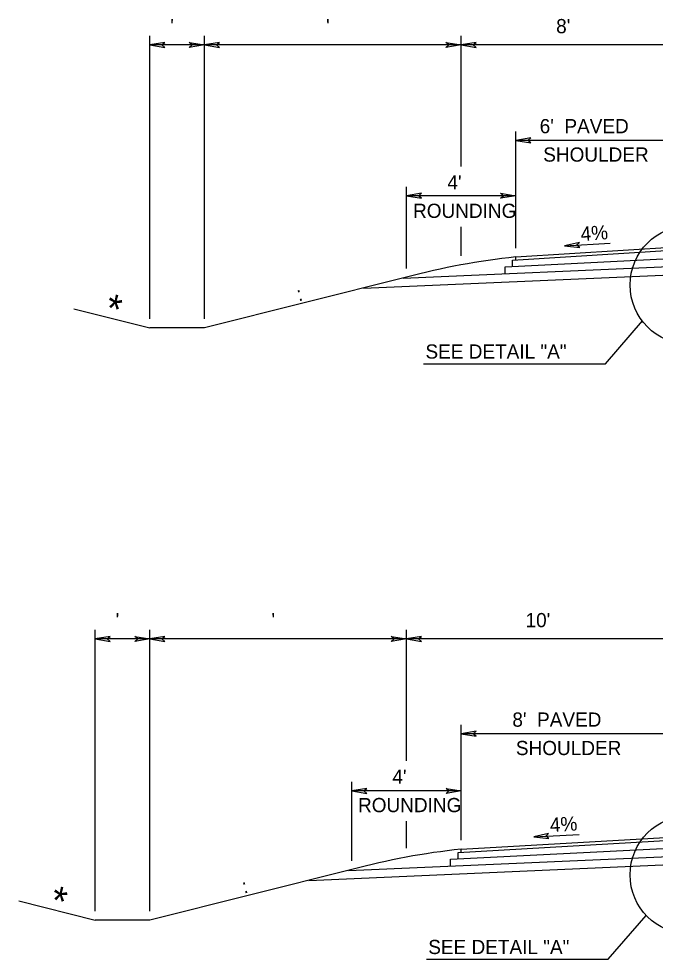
# Model space of a CAD drawing. Extents: x -592 to 1199, y -590 to 416.
# Drawn here: x -418.4 to -355.6, y 57.8 to 150.5 of the extents above; entities that cross this region are included whole.
import ezdxf

# ---------------------------------------------------------------- set-up
doc = ezdxf.new("R2010")
doc.units = 0
doc.layers.add('1', color=7, linetype='Continuous')
doc.layers.add('Des_ Drain_ Ftrs', color=7, linetype='Continuous')

msp = doc.modelspace()

# ---------------------------------------------------------------- linework, layer by layer
at = {"layer": '1'}
for p, q in [((-405.485, 120.951), (-405.485, 148.844)), ((-400.096, 120.951), (-400.096, 148.844)), ((-374.782, 135.971), (-374.782, 148.844)), ((-400.096, 147.964), (-405.485, 147.964)), ((-374.782, 147.964), (-400.096, 147.964)), ((-353.229, 147.964), (-374.782, 147.964)), ((-369.384, 127.944), (-369.384, 139.437)), ((-353.229, 138.557), (-369.384, 138.557)), ((-380.16, 125.935), (-380.16, 133.976)), ((-369.384, 133.096), (-380.16, 133.096)), ((-374.782, 127.165), (-374.782, 130.034)), ((-369.384, 127.064), (-353.234, 128.08)), ((-364.574, 128.144), (-360.084, 128.429)), ((-380.489, 124.973), (-326.288, 127.339)), ((-369.688, 126.744), (-353.469, 127.767)), ((-369.384, 126.764), (-369.384, 127.064)), ((-370.415, 126.097), (-354.173, 126.918)), ((-370.415, 125.413), (-370.415, 126.097)), ((-369.688, 126.134), (-369.688, 126.744)), ((-384.414, 123.991), (-354.876, 125.282)), ((-380.16, 125.055), (-400.096, 120.071)), ((-412.962, 121.94), (-405.485, 120.071)), ((-360.543, 116.54), (-356.895, 120.754)), ((-400.096, 120.071), (-405.485, 120.071)), ((-378.474, 116.54), (-360.543, 116.54)), ((-410.871, 62.58), (-410.871, 90.297)), ((-405.482, 62.58), (-405.482, 90.297)), ((-380.173, 77.411), (-380.173, 90.297)), ((-405.482, 89.417), (-410.871, 89.417)), ((-380.173, 89.417), (-405.482, 89.417)), ((-353.231, 89.417), (-380.173, 89.417)), ((-374.775, 69.563), (-374.775, 80.943)), ((-353.231, 80.063), (-374.775, 80.063)), ((-385.551, 67.555), (-385.551, 75.318)), ((-374.775, 74.438), (-385.551, 74.438)), ((-380.173, 68.785), (-380.173, 71.461)), ((-375.079, 68.366), (-353.471, 69.626)), ((-374.775, 68.684), (-353.237, 69.935)), ((-367.61, 69.9), (-363.119, 70.149)), ((-385.878, 66.593), (-326.29, 69.195)), ((-375.806, 67.718), (-354.175, 68.787)), ((-374.774, 68.383), (-374.774, 68.683)), ((-375.806, 67.033), (-375.806, 67.718)), ((-375.079, 67.754), (-375.079, 68.366)), ((-389.798, 65.613), (-354.879, 67.138)), ((-385.551, 66.675), (-405.482, 61.7)), ((-418.406, 63.584), (-410.871, 61.7)), ((-360.266, 57.846), (-356.526, 62.166)), ((-405.482, 61.7), (-410.871, 61.7)), ((-378.198, 57.846), (-360.266, 57.846))]:
    msp.add_line(p, q, dxfattribs=at)
for centre in [(-352.264, 124.302), (-352.266, 66.158)]:
    msp.add_circle(centre, 5.838, dxfattribs=at)
for centre in [(-362.501, 60.229), (-367.892, 1.849)]:
    msp.add_arc(centre, 67.188, 95.87953, 105.23809, dxfattribs=at)
at = {"layer": 'Des_ Drain_ Ftrs'}
for points in [[(-405.485, 147.964), (-403.997, 147.716), (-404.292, 147.964), (-403.997, 148.213)], [(-400.096, 147.964), (-401.585, 147.716), (-401.29, 147.964), (-401.585, 148.213)], [(-400.096, 147.964), (-398.608, 147.716), (-398.903, 147.964), (-398.608, 148.213)], [(-374.782, 147.964), (-376.271, 147.716), (-375.976, 147.964), (-376.271, 148.213)], [(-374.782, 147.964), (-373.294, 147.716), (-373.589, 147.964), (-373.294, 148.213)], [(-369.384, 138.557), (-367.895, 138.308), (-368.19, 138.557), (-367.895, 138.805)], [(-380.16, 133.096), (-378.672, 132.848), (-378.967, 133.096), (-378.672, 133.344)], [(-369.384, 133.096), (-370.872, 132.848), (-370.577, 133.096), (-370.872, 133.344)], [(-364.574, 128.144), (-363.073, 127.989), (-363.383, 128.219), (-363.104, 128.485)], [(-410.871, 89.417), (-409.383, 89.168), (-409.678, 89.417), (-409.383, 89.665)], [(-405.482, 89.417), (-406.971, 89.168), (-406.676, 89.417), (-406.971, 89.665)], [(-405.482, 89.417), (-403.994, 89.168), (-404.289, 89.417), (-403.994, 89.665)], [(-380.173, 89.417), (-381.662, 89.168), (-381.367, 89.417), (-381.662, 89.665)], [(-380.173, 89.417), (-378.685, 89.168), (-378.98, 89.417), (-378.685, 89.665)], [(-374.775, 80.063), (-373.286, 79.815), (-373.581, 80.063), (-373.286, 80.311)], [(-385.551, 74.438), (-384.063, 74.19), (-384.358, 74.438), (-384.063, 74.686)], [(-374.775, 74.438), (-376.263, 74.19), (-375.968, 74.438), (-376.263, 74.686)], [(-367.61, 69.9), (-366.111, 69.733), (-366.419, 69.965), (-366.138, 70.229)]]:
    msp.add_lwpolyline(points, close=True, dxfattribs=at)

# ---------------------------------------------------------------- texts
at = {"layer": '1'}
for s, p in [(" '", (-403.986, 149.116)), ("  '", (-389.135, 149.116)), ("8'", (-365.396, 149.116)), ("6'  PAVED", (-367.022, 139.257)), ('SHOULDER', (-366.673, 136.457)), ("4'", (-376.124, 133.712)), ('ROUNDING', (-379.513, 130.912)), ('SEE DETAIL "A"', (-378.289, 117.043)), (" '", (-409.372, 90.568)), ("  '", (-394.524, 90.568)), ("10'", (-368.417, 90.568)), ("8'  PAVED", (-369.719, 80.763)), ('SHOULDER', (-369.37, 77.963)), ("4'", (-381.553, 75.138)), ('ROUNDING', (-384.942, 72.338)), ('SEE DETAIL "A"', (-378.013, 58.35))]:
    msp.add_text(s, height=1.4, dxfattribs=at).set_placement(p)
for s, height, rotation, p in [('4%', 1.4, 3.91556, (-362.941, 128.632)), ('*', 2.8, 347.15207, (-410.049, 120.76)), (' : ', 1.4, 14.22821, (-391.308, 122.55)), ('4%', 1.4, 3.46407, (-365.975, 70.374)), ('*', 2.8, 347.15207, (-415.464, 62.397)), (' : ', 1.4, 14.22821, (-396.696, 64.175))]:
    msp.add_text(s, height=height, rotation=rotation, dxfattribs=at).set_placement(p)

doc.saveas('drawing.dxf')
